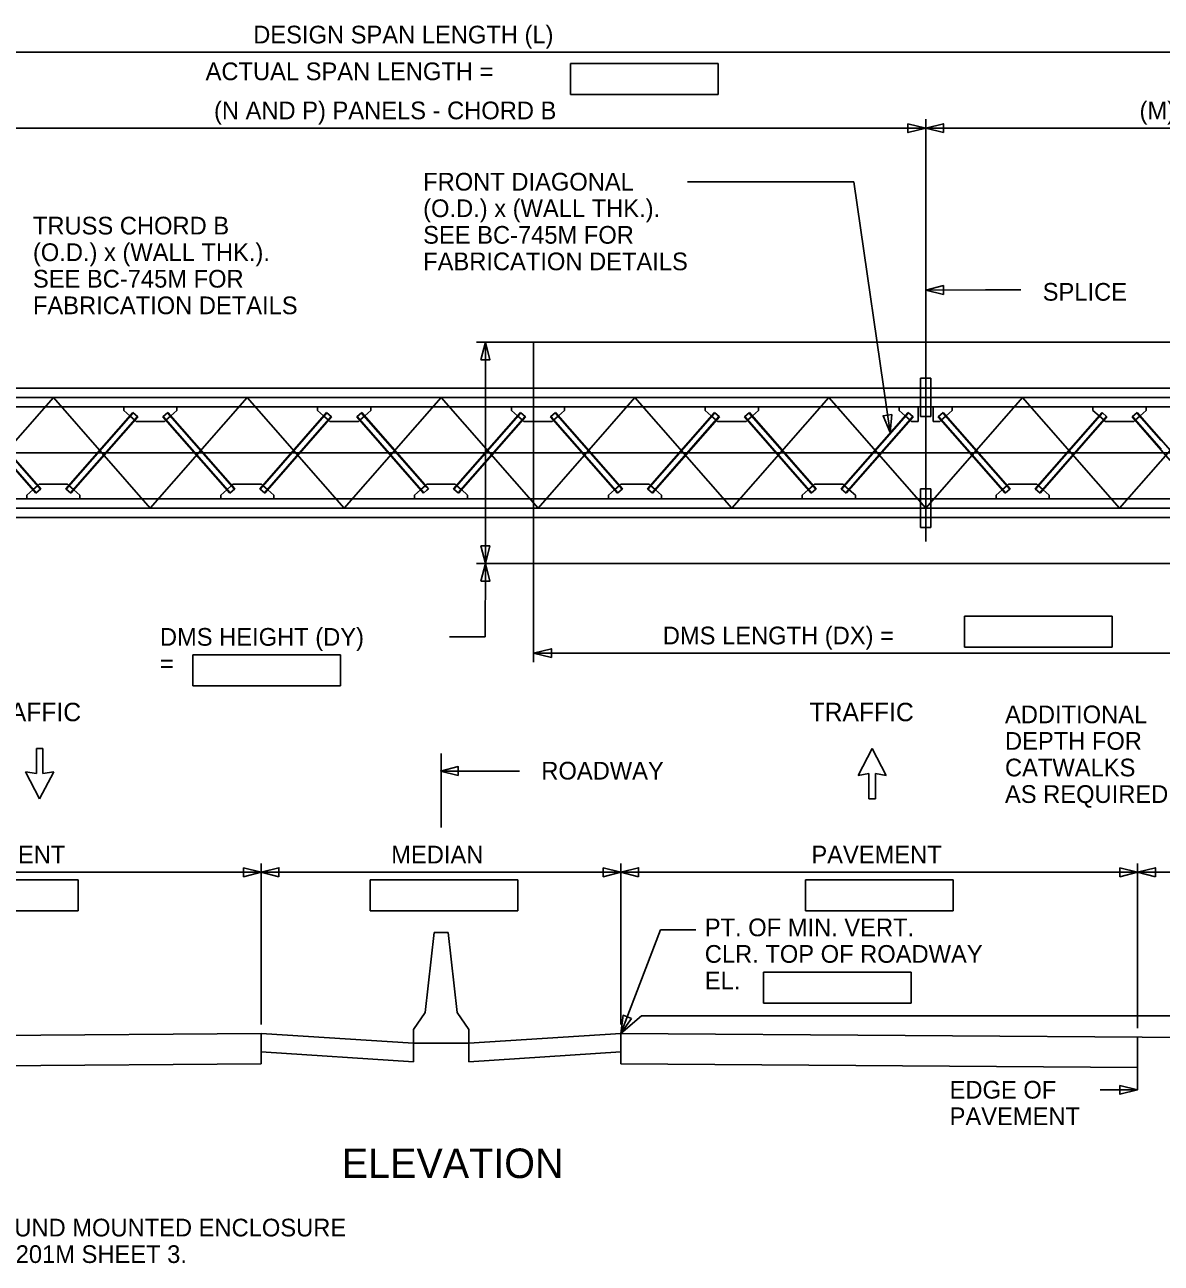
# Model space of a CAD drawing. Extents: x 3831399 to 3833095, y 499014 to 500202.
# Drawn here: x 3832471.3 to 3832657.9, y 499766.4 to 499969.9 of the extents above; entities that cross this region are included whole.
import ezdxf

# ---------------------------------------------------------------- set-up
doc = ezdxf.new("R2010")
doc.units = 0
for name, color, linetype in [('0-sign', 7, 'Continuous'), ('0-truss', 7, 'Continuous'), ('CenterLine', 7, 'Continuous'), ('Default', 7, 'Continuous'), ('DIM TXT', 7, 'Continuous'), ('grade', 7, 'Continuous')]:
    doc.layers.add(name, color=color, linetype=linetype)

msp = doc.modelspace()

# ---------------------------------------------------------------- linework, layer by layer
at = {"layer": '0-sign'}
for p, q in [((3832668.48, 499917.74), (3832554.81, 499917.74)), ((3832554.81, 499917.74), (3832554.81, 499881.36)), ((3832554.81, 499881.36), (3832668.48, 499881.36))]:
    msp.add_line(p, q, dxfattribs=at)
at = {"layer": '0-truss'}
for p, q in [((3832619.18, 499911.79), (3832618.33, 499911.79)), ((3832618.33, 499911.79), (3832618.33, 499905.49)), ((3832619.18, 499905.49), (3832619.18, 499911.79)), ((3832619.18, 499911.79), (3832620.03, 499911.79)), ((3832619.18, 499905.49), (3832619.18, 499911.79)), ((3832620.03, 499911.79), (3832620.03, 499905.49)), ((3832460.9, 499910.16), (3832537.29, 499910.16)), ((3832537.29, 499910.16), (3832650.95, 499910.16)), ((3832537.29, 499910.16), (3832685.48, 499910.16)), ((3832460.9, 499907.13), (3832537.29, 499907.13)), ((3832537.29, 499907.13), (3832650.95, 499907.13)), ((3832537.29, 499907.13), (3832685.48, 499907.13)), ((3832617.95, 499904.71), (3832617.95, 499907.13)), ((3832620.41, 499904.71), (3832620.41, 499907.13)), ((3832650.95, 499907.13), (3832646.65, 499907.13)), ((3832646.65, 499907.13), (3832646.65, 499906.48)), ((3832473.08, 499892.92), (3832462.1, 499905.47)), ((3832462.16, 499905.52), (3832473.14, 499892.97)), ((3832462.86, 499906.13), (3832473.84, 499893.58)), ((3832462.92, 499906.18), (3832473.9, 499893.63)), ((3832489, 499906.18), (3832478.02, 499893.63)), ((3832489.05, 499906.13), (3832478.07, 499893.58)), ((3832489.76, 499905.52), (3832478.78, 499892.97)), ((3832478.84, 499892.92), (3832489.82, 499905.47)), ((3832487.52, 499906.48), (3832488.5, 499905.62)), ((3832488.5, 499905.62), (3832489.32, 499904.9)), ((3832489.82, 499905.47), (3832489, 499906.18)), ((3832489.32, 499904.9), (3832489.53, 499904.71)), ((3832493.93, 499905.47), (3832494.75, 499906.18)), ((3832504.91, 499892.92), (3832493.93, 499905.47)), ((3832493.99, 499905.52), (3832504.97, 499892.97)), ((3832494.21, 499904.71), (3832494.42, 499904.9)), ((3832494.42, 499904.9), (3832495.24, 499905.62)), ((3832494.69, 499906.13), (3832505.67, 499893.58)), ((3832494.75, 499906.18), (3832505.73, 499893.63)), ((3832495.24, 499905.62), (3832496.23, 499906.48)), ((3832520.82, 499906.18), (3832509.84, 499893.63)), ((3832520.88, 499906.13), (3832509.9, 499893.58)), ((3832521.58, 499905.52), (3832510.6, 499892.97)), ((3832510.66, 499892.92), (3832521.64, 499905.47)), ((3832519.34, 499906.48), (3832520.33, 499905.62)), ((3832520.33, 499905.62), (3832521.15, 499904.9)), ((3832521.64, 499905.47), (3832520.82, 499906.18)), ((3832521.15, 499904.9), (3832521.36, 499904.71)), ((3832525.76, 499905.47), (3832526.58, 499906.18)), ((3832536.74, 499892.92), (3832525.76, 499905.47)), ((3832525.81, 499905.52), (3832536.79, 499892.97)), ((3832526.04, 499904.71), (3832526.25, 499904.9)), ((3832526.25, 499904.9), (3832527.07, 499905.62)), ((3832526.52, 499906.13), (3832537.29, 499893.83)), ((3832526.58, 499906.18), (3832537.29, 499893.94)), ((3832527.07, 499905.62), (3832528.06, 499906.48)), ((3832552.65, 499906.18), (3832541.67, 499893.63)), ((3832552.71, 499906.13), (3832541.73, 499893.58)), ((3832553.41, 499905.52), (3832542.43, 499892.97)), ((3832542.49, 499892.92), (3832553.47, 499905.47)), ((3832552.15, 499905.62), (3832551.17, 499906.48)), ((3832552.97, 499904.9), (3832552.15, 499905.62)), ((3832553.47, 499905.47), (3832552.65, 499906.18)), ((3832553.19, 499904.71), (3832552.97, 499904.9)), ((3832557.58, 499905.47), (3832558.4, 499906.18)), ((3832568.56, 499892.92), (3832557.58, 499905.47)), ((3832557.64, 499905.52), (3832568.62, 499892.97)), ((3832558.08, 499904.9), (3832557.87, 499904.71)), ((3832558.9, 499905.62), (3832558.08, 499904.9)), ((3832558.35, 499906.13), (3832569.33, 499893.58)), ((3832558.4, 499906.18), (3832569.38, 499893.63)), ((3832559.88, 499906.48), (3832558.9, 499905.62)), ((3832584.48, 499906.18), (3832573.5, 499893.63)), ((3832584.54, 499906.13), (3832573.56, 499893.58)), ((3832585.24, 499905.52), (3832574.26, 499892.97)), ((3832574.32, 499892.92), (3832585.3, 499905.47)), ((3832583.98, 499905.62), (3832583, 499906.48)), ((3832584.8, 499904.9), (3832583.98, 499905.62)), ((3832585.3, 499905.47), (3832584.48, 499906.18)), ((3832585.02, 499904.71), (3832584.8, 499904.9)), ((3832589.41, 499905.47), (3832590.23, 499906.18)), ((3832600.39, 499892.92), (3832589.41, 499905.47)), ((3832589.47, 499905.52), (3832600.45, 499892.97)), ((3832589.91, 499904.9), (3832589.69, 499904.71)), ((3832590.73, 499905.62), (3832589.91, 499904.9)), ((3832590.17, 499906.13), (3832601.15, 499893.58)), ((3832590.23, 499906.18), (3832601.21, 499893.63)), ((3832591.71, 499906.48), (3832590.73, 499905.62)), ((3832616.3, 499906.18), (3832605.32, 499893.63)), ((3832616.36, 499906.13), (3832605.38, 499893.58)), ((3832617.07, 499905.52), (3832606.09, 499892.97)), ((3832606.14, 499892.92), (3832617.12, 499905.47)), ((3832614.82, 499906.48), (3832615.81, 499905.62)), ((3832616.63, 499904.9), (3832615.81, 499905.62)), ((3832617.12, 499905.47), (3832616.3, 499906.18)), ((3832616.63, 499904.9), (3832616.84, 499904.71)), ((3832616.84, 499904.71), (3832617.95, 499904.71)), ((3832617.95, 499904.71), (3832617.95, 499904.71)), ((3832618.33, 499905.49), (3832619.18, 499905.49)), ((3832620.03, 499905.49), (3832619.18, 499905.49)), ((3832621.52, 499904.71), (3832620.41, 499904.71)), ((3832620.41, 499904.71), (3832620.41, 499904.71)), ((3832621.24, 499905.47), (3832622.06, 499906.18)), ((3832632.22, 499892.92), (3832621.24, 499905.47)), ((3832621.3, 499905.52), (3832632.28, 499892.97)), ((3832621.73, 499904.9), (3832621.52, 499904.71)), ((3832621.73, 499904.9), (3832622.55, 499905.62)), ((3832622, 499906.13), (3832632.98, 499893.58)), ((3832622.06, 499906.18), (3832633.04, 499893.63)), ((3832623.54, 499906.48), (3832622.55, 499905.62)), ((3832648.13, 499906.18), (3832637.15, 499893.63)), ((3832648.19, 499906.13), (3832637.21, 499893.58)), ((3832648.89, 499905.52), (3832637.91, 499892.97)), ((3832637.97, 499892.92), (3832648.95, 499905.47)), ((3832646.65, 499906.48), (3832647.64, 499905.62)), ((3832647.64, 499905.62), (3832648.46, 499904.9)), ((3832648.95, 499905.47), (3832648.13, 499906.18)), ((3832648.46, 499904.9), (3832648.67, 499904.71)), ((3832648.67, 499904.71), (3832650.95, 499904.71)), ((3832653.07, 499905.47), (3832653.89, 499906.18)), ((3832657.84, 499900.01), (3832653.07, 499905.47)), ((3832653.12, 499905.52), (3832657.84, 499900.13)), ((3832653.35, 499904.71), (3832653.56, 499904.9)), ((3832653.56, 499904.9), (3832654.38, 499905.62)), ((3832653.83, 499906.13), (3832657.84, 499901.55)), ((3832653.89, 499906.18), (3832657.84, 499901.66)), ((3832654.38, 499905.62), (3832655.37, 499906.48)), ((3832657.84, 499901.66), (3832659.33, 499899.96)), ((3832657.84, 499900.01), (3832659.33, 499898.3)), ((3832472.59, 499893.48), (3832471.6, 499892.62)), ((3832472.59, 499893.48), (3832473.41, 499894.2)), ((3832473.9, 499893.63), (3832473.08, 499892.92)), ((3832473.62, 499894.39), (3832473.41, 499894.2)), ((3832478.02, 499893.63), (3832478.84, 499892.92)), ((3832478.51, 499894.2), (3832478.3, 499894.39)), ((3832478.51, 499894.2), (3832479.33, 499893.48)), ((3832480.32, 499892.62), (3832479.33, 499893.48)), ((3832504.41, 499893.48), (3832503.43, 499892.62)), ((3832504.41, 499893.48), (3832505.23, 499894.2)), ((3832505.73, 499893.63), (3832504.91, 499892.92)), ((3832505.45, 499894.39), (3832505.23, 499894.2)), ((3832509.84, 499893.63), (3832510.66, 499892.92)), ((3832510.34, 499894.2), (3832510.12, 499894.39)), ((3832510.34, 499894.2), (3832511.16, 499893.48)), ((3832512.14, 499892.62), (3832511.16, 499893.48)), ((3832535.26, 499892.62), (3832536.24, 499893.48)), ((3832536.24, 499893.48), (3832537.06, 499894.2)), ((3832537.29, 499893.4), (3832536.74, 499892.92)), ((3832537.06, 499894.2), (3832537.27, 499894.39)), ((3832537.29, 499894.39), (3832541.95, 499894.39)), ((3832537.29, 499893.94), (3832537.56, 499893.63)), ((3832537.56, 499893.63), (3832537.29, 499893.4)), ((3832541.67, 499893.63), (3832542.49, 499892.92)), ((3832541.95, 499894.39), (3832542.17, 499894.2)), ((3832542.99, 499893.48), (3832542.17, 499894.2)), ((3832542.96, 499893.5), (3832543.97, 499892.62)), ((3832543.97, 499892.62), (3832543.97, 499891.97)), ((3832567.08, 499892.62), (3832568.07, 499893.48)), ((3832568.89, 499894.2), (3832568.07, 499893.48)), ((3832569.38, 499893.63), (3832568.56, 499892.92)), ((3832568.89, 499894.2), (3832569.1, 499894.39)), ((3832573.5, 499893.63), (3832574.32, 499892.92)), ((3832573.78, 499894.39), (3832573.99, 499894.2)), ((3832574.81, 499893.48), (3832573.99, 499894.2)), ((3832574.81, 499893.48), (3832575.8, 499892.62)), ((3832598.91, 499892.62), (3832599.9, 499893.48)), ((3832600.72, 499894.2), (3832599.9, 499893.48)), ((3832601.21, 499893.63), (3832600.39, 499892.92)), ((3832600.72, 499894.2), (3832600.93, 499894.39)), ((3832605.32, 499893.63), (3832606.14, 499892.92)), ((3832605.61, 499894.39), (3832605.82, 499894.2)), ((3832606.64, 499893.48), (3832605.82, 499894.2)), ((3832606.64, 499893.48), (3832607.63, 499892.62)), ((3832618.33, 499893.61), (3832619.18, 499893.61)), ((3832618.33, 499887.31), (3832618.33, 499893.61)), ((3832620.03, 499893.61), (3832619.18, 499893.61)), ((3832619.18, 499893.61), (3832619.18, 499887.31)), ((3832619.18, 499893.61), (3832619.18, 499887.31)), ((3832620.03, 499887.31), (3832620.03, 499893.61)), ((3832631.72, 499893.48), (3832630.74, 499892.62)), ((3832631.72, 499893.48), (3832632.54, 499894.2)), ((3832633.04, 499893.63), (3832632.22, 499892.92)), ((3832632.76, 499894.39), (3832632.54, 499894.2)), ((3832637.15, 499893.63), (3832637.97, 499892.92)), ((3832637.65, 499894.2), (3832637.43, 499894.39)), ((3832637.65, 499894.2), (3832638.47, 499893.48)), ((3832639.45, 499892.62), (3832638.47, 499893.48)), ((3832460.9, 499891.97), (3832537.29, 499891.97)), ((3832537.29, 499891.97), (3832650.95, 499891.97)), ((3832537.29, 499891.97), (3832685.48, 499891.97)), ((3832543.97, 499891.97), (3832537.29, 499891.97)), ((3832460.9, 499888.94), (3832537.29, 499888.94)), ((3832537.29, 499888.94), (3832650.95, 499888.94)), ((3832537.29, 499888.94), (3832650.95, 499888.94)), ((3832650.95, 499888.94), (3832685.48, 499888.94)), ((3832619.18, 499887.31), (3832618.33, 499887.31)), ((3832619.18, 499887.31), (3832620.03, 499887.31))]:
    msp.add_line(p, q, dxfattribs=at)
for points in [[(3832496.23, 499906.48), (3832496.23, 499907.13), (3832487.52, 499907.13), (3832487.52, 499906.48)], [(3832528.06, 499906.48), (3832528.06, 499907.13), (3832519.34, 499907.13), (3832519.34, 499906.48)], [(3832551.17, 499906.48), (3832551.17, 499907.13), (3832559.88, 499907.13), (3832559.88, 499906.48)], [(3832583, 499906.48), (3832583, 499907.13), (3832591.71, 499907.13), (3832591.71, 499906.48)], [(3832617.95, 499907.13), (3832614.82, 499907.13), (3832614.82, 499906.48)], [(3832620.41, 499907.13), (3832623.54, 499907.13), (3832623.54, 499906.48)], [(3832655.37, 499906.48), (3832655.37, 499907.13), (3832650.95, 499907.13)], [(3832489.53, 499904.71), (3832494.21, 499904.71)], [(3832521.36, 499904.71), (3832526.04, 499904.71)], [(3832557.87, 499904.71), (3832553.19, 499904.71)], [(3832589.69, 499904.71), (3832585.02, 499904.71)], [(3832650.95, 499904.71), (3832653.35, 499904.71)], [(3832471.6, 499892.62), (3832471.6, 499891.97), (3832480.32, 499891.97), (3832480.32, 499892.62)], [(3832478.3, 499894.39), (3832473.62, 499894.39)], [(3832503.43, 499892.62), (3832503.43, 499891.97), (3832512.14, 499891.97), (3832512.14, 499892.62)], [(3832510.12, 499894.39), (3832505.45, 499894.39)], [(3832537.29, 499891.97), (3832535.26, 499891.97), (3832535.26, 499892.62)], [(3832537.27, 499894.39), (3832537.29, 499894.39)], [(3832575.8, 499892.62), (3832575.8, 499891.97), (3832567.08, 499891.97), (3832567.08, 499892.62)], [(3832569.1, 499894.39), (3832573.78, 499894.39)], [(3832607.63, 499892.62), (3832607.63, 499891.97), (3832598.91, 499891.97), (3832598.91, 499892.62)], [(3832600.93, 499894.39), (3832605.61, 499894.39)], [(3832630.74, 499892.62), (3832630.74, 499891.97), (3832639.45, 499891.97), (3832639.45, 499892.62)], [(3832637.43, 499894.39), (3832632.76, 499894.39)]]:
    msp.add_lwpolyline(points, dxfattribs=at)
at = {"layer": 'CenterLine'}
for p, q in [((3832619.18, 499936.04), (3832619.18, 499885)), ((3832332.74, 499908.64), (3832746.49, 499908.64)), ((3832475.96, 499908.64), (3832460.05, 499890.46)), ((3832475.96, 499908.64), (3832491.87, 499890.46)), ((3832507.79, 499908.64), (3832491.87, 499890.46)), ((3832507.79, 499908.64), (3832523.7, 499890.46)), ((3832539.61, 499908.64), (3832523.7, 499890.46)), ((3832539.61, 499908.64), (3832555.53, 499890.46)), ((3832571.44, 499908.64), (3832555.53, 499890.46)), ((3832571.44, 499908.64), (3832587.35, 499890.46)), ((3832603.27, 499908.64), (3832587.35, 499890.46)), ((3832603.27, 499908.64), (3832619.18, 499890.46)), ((3832635.1, 499908.64), (3832619.18, 499890.46)), ((3832635.1, 499908.64), (3832651.01, 499890.46)), ((3832666.92, 499908.64), (3832651.01, 499890.46)), ((3832308.87, 499899.55), (3832771.9, 499899.55)), ((3832332.74, 499890.46), (3832746.49, 499890.46))]:
    msp.add_line(p, q, dxfattribs=at)
at = {"layer": 'Default'}
for p, q in [((3832560.85, 499963.52), (3832585.1, 499963.52)), ((3832560.85, 499958.43), (3832560.85, 499963.52)), ((3832585.1, 499963.52), (3832585.1, 499958.43)), ((3832585.1, 499958.43), (3832560.85, 499958.43)), ((3832625.55, 499872.74), (3832649.8, 499872.74)), ((3832625.55, 499867.65), (3832625.55, 499872.74)), ((3832649.8, 499872.74), (3832649.8, 499867.65)), ((3832498.87, 499866.36), (3832523.12, 499866.36)), ((3832498.87, 499861.26), (3832498.87, 499866.36)), ((3832523.12, 499866.36), (3832523.12, 499861.26)), ((3832649.8, 499867.65), (3832625.55, 499867.65)), ((3832523.12, 499861.26), (3832498.87, 499861.26)), ((3832539.61, 499838.03), (3832539.61, 499850.15)), ((3832455.78, 499829.38), (3832480.03, 499829.38)), ((3832480.03, 499829.38), (3832480.03, 499824.29)), ((3832527.96, 499829.38), (3832552.21, 499829.38)), ((3832527.96, 499824.29), (3832527.96, 499829.38)), ((3832552.21, 499829.38), (3832552.21, 499824.29)), ((3832599.43, 499829.38), (3832623.68, 499829.38)), ((3832599.43, 499824.29), (3832599.43, 499829.38)), ((3832623.68, 499829.38), (3832623.68, 499824.29)), ((3832480.03, 499824.29), (3832455.78, 499824.29)), ((3832552.21, 499824.29), (3832527.96, 499824.29)), ((3832623.68, 499824.29), (3832599.43, 499824.29)), ((3832592.55, 499814.26), (3832616.8, 499814.26)), ((3832592.55, 499809.16), (3832592.55, 499814.26)), ((3832616.8, 499814.26), (3832616.8, 499809.16)), ((3832616.8, 499809.16), (3832592.55, 499809.16))]:
    msp.add_line(p, q, dxfattribs=at)
at = {"layer": 'DIM TXT'}
for p, q in [((3832332.74, 499965.35), (3832746.37, 499965.35)), ((3832619.18, 499954.34), (3832619.18, 499954.34)), ((3832619.18, 499936.04), (3832619.18, 499954.34)), ((3832460.05, 499952.88), (3832619.18, 499952.88)), ((3832619.18, 499952.88), (3832746.49, 499952.88)), ((3832601.55, 499944.09), (3832580.07, 499944.09)), ((3832601.55, 499944.09), (3832607.37, 499944.09)), ((3832613.33, 499902.87), (3832607.37, 499944.09)), ((3832619.18, 499926.27), (3832628.98, 499926.32)), ((3832634.8, 499926.32), (3832628.98, 499926.32)), ((3832554.81, 499917.74), (3832545.43, 499917.74)), ((3832546.89, 499917.74), (3832546.89, 499881.36)), ((3832554.81, 499881.36), (3832545.43, 499881.36)), ((3832546.89, 499881.36), (3832546.83, 499869.32)), ((3832554.81, 499881.36), (3832554.81, 499865.18)), ((3832541.01, 499869.32), (3832546.83, 499869.32)), ((3832554.81, 499866.64), (3832668.48, 499866.64)), ((3832474.22, 499850.98), (3832473.17, 499850.98)), ((3832473.17, 499850.98), (3832473.17, 499846.85)), ((3832474.22, 499846.85), (3832474.22, 499850.98)), ((3832608.08, 499846.56), (3832610.4, 499850.98)), ((3832610.4, 499850.98), (3832612.71, 499846.56)), ((3832473.17, 499846.85), (3832471.38, 499847.15)), ((3832471.38, 499847.15), (3832473.69, 499842.73)), ((3832473.69, 499842.73), (3832476.01, 499847.15)), ((3832476.01, 499847.15), (3832474.22, 499846.85)), ((3832539.53, 499847.27), (3832546.65, 499847.27)), ((3832552.47, 499847.27), (3832546.65, 499847.27)), ((3832609.87, 499846.85), (3832608.08, 499846.56)), ((3832609.87, 499842.73), (3832609.87, 499846.85)), ((3832610.92, 499846.85), (3832610.92, 499842.73)), ((3832612.71, 499846.56), (3832610.92, 499846.85)), ((3832610.92, 499842.73), (3832609.87, 499842.73)), ((3832510.09, 499805.63), (3832510.09, 499832.1)), ((3832510.09, 499807.08), (3832510.09, 499832.1)), ((3832569.14, 499805.63), (3832569.14, 499832.1)), ((3832569.14, 499807.08), (3832569.14, 499832.1)), ((3832653.98, 499805.02), (3832653.98, 499832.1)), ((3832653.98, 499806.48), (3832653.98, 499832.1)), ((3832510.09, 499830.65), (3832425.25, 499830.65)), ((3832510.09, 499830.65), (3832569.14, 499830.65)), ((3832569.14, 499830.65), (3832653.98, 499830.65)), ((3832653.98, 499830.65), (3832697.19, 499830.65)), ((3832569.14, 499804.17), (3832575.64, 499821.22)), ((3832581.46, 499821.22), (3832575.64, 499821.22)), ((3832569.14, 499804.17), (3832572.52, 499807.09)), ((3832572.52, 499807.09), (3832680.32, 499807.09)), ((3832653.98, 499798.56), (3832653.98, 499794.93)), ((3832647.84, 499794.93), (3832653.66, 499794.93)), ((3832653.98, 499794.93), (3832653.66, 499794.93))]:
    msp.add_line(p, q, dxfattribs=at)
for points in [[(3832616.27, 499953.61), (3832619.18, 499952.88), (3832616.27, 499952.16)], [(3832622.09, 499952.16), (3832619.18, 499952.88), (3832622.09, 499953.61)], [(3832622.1, 499925.55), (3832619.18, 499926.27), (3832622.09, 499927.01)], [(3832546.16, 499914.83), (3832546.89, 499917.74), (3832547.62, 499914.83)], [(3832613.63, 499905.85), (3832613.33, 499902.87), (3832612.19, 499905.64)], [(3832547.62, 499884.27), (3832546.89, 499881.36), (3832546.16, 499884.27)], [(3832546.15, 499878.46), (3832546.89, 499881.36), (3832547.6, 499878.45)], [(3832557.72, 499865.91), (3832554.81, 499866.64), (3832557.72, 499867.36)], [(3832542.44, 499846.54), (3832539.53, 499847.27), (3832542.44, 499848)], [(3832507.18, 499831.38), (3832510.09, 499830.65), (3832507.18, 499829.92)], [(3832513, 499829.92), (3832510.09, 499830.65), (3832513, 499831.38)], [(3832566.23, 499831.38), (3832569.14, 499830.65), (3832566.23, 499829.92)], [(3832572.05, 499829.92), (3832569.14, 499830.65), (3832572.05, 499831.38)], [(3832651.07, 499831.38), (3832653.98, 499830.65), (3832651.07, 499829.92)], [(3832656.89, 499829.92), (3832653.98, 499830.65), (3832656.89, 499831.38)], [(3832570.86, 499806.63), (3832569.14, 499804.17), (3832569.5, 499807.15)], [(3832651.06, 499795.65), (3832653.98, 499794.93), (3832651.07, 499794.19)]]:
    msp.add_lwpolyline(points, close=True, dxfattribs=at)
at = {"layer": 'grade'}
for p, q in [((3832536.98, 499807.61), (3832538.48, 499820.74)), ((3832540.75, 499820.74), (3832538.48, 499820.74)), ((3832539.61, 499820.74), (3832540.75, 499820.74)), ((3832542.25, 499807.61), (3832540.75, 499820.74)), ((3832535.07, 499804.83), (3832536.98, 499807.61)), ((3832544.16, 499804.83), (3832542.25, 499807.61)), ((3832352.64, 499803.05), (3832510.09, 499804.17)), ((3832510.09, 499804.17), (3832535.07, 499802.56)), ((3832510.09, 499799.16), (3832510.09, 499804.17)), ((3832535.07, 499802.56), (3832535.07, 499804.83)), ((3832544.16, 499802.56), (3832544.16, 499804.83)), ((3832569.14, 499804.17), (3832544.16, 499802.56)), ((3832726.58, 499803.05), (3832569.14, 499804.17)), ((3832569.14, 499801.14), (3832569.14, 499804.17)), ((3832569.14, 499799.16), (3832569.14, 499804.17)), ((3832653.98, 499798.67), (3832653.98, 499803.57)), ((3832653.98, 499798.56), (3832653.98, 499803.57)), ((3832510.09, 499801.14), (3832535.07, 499799.52)), ((3832539.61, 499802.56), (3832535.07, 499802.56)), ((3832535.07, 499802.56), (3832535.07, 499799.52)), ((3832539.61, 499802.56), (3832544.16, 499802.56)), ((3832544.16, 499802.56), (3832544.16, 499799.52)), ((3832569.14, 499801.14), (3832544.16, 499799.52)), ((3832425.25, 499798.56), (3832510.09, 499799.16)), ((3832653.97, 499798.56), (3832569.14, 499799.16))]:
    msp.add_line(p, q, dxfattribs=at)

# ---------------------------------------------------------------- texts
at = {"layer": 'DIM TXT'}
for s, height, p in [('DESIGN SPAN LENGTH (L)', 2.9099, (3832508.77, 499966.8)), ('ACTUAL SPAN LENGTH = ', 2.9099, (3832500.95, 499960.76)), ('(N AND P) PANELS - CHORD B', 2.9099, (3832502.33, 499954.34)), ('(M) PANELS - CHORD C', 2.9099, (3832654.29, 499954.34)), ('FRONT DIAGONAL', 2.9099, (3832536.67, 499942.63)), ('(O.D.) x (WALL THK.).', 2.9099, (3832536.67, 499938.27)), ('TRUSS CHORD B', 2.9099, (3832472.6, 499935.42)), ('SEE BC-745M FOR', 2.9099, (3832536.67, 499933.9)), ('(O.D.) x (WALL THK.).', 2.9099, (3832472.6, 499931.05)), ('FABRICATION DETAILS', 2.9099, (3832536.67, 499929.54)), ('SEE BC-745M FOR', 2.9099, (3832472.6, 499926.69)), ('  SPLICE', 2.91, (3832636.23, 499924.54)), ('FABRICATION DETAILS', 2.9099, (3832472.6, 499922.32)), ('DMS HEIGHT (DY)', 2.9099, (3832493.45, 499867.86)), ('DMS LENGTH (DX) =        ', 2.9099, (3832576.02, 499868.09)), ('=', 2.91, (3832493.45, 499863.5)), ('TRAFFIC', 3.031, (3832463.4, 499855.46)), ('TRAFFIC', 3.031, (3832600.11, 499855.46)), ('ADDITIONAL', 2.91, (3832632.2, 499855.13)), ('DEPTH FOR', 2.91, (3832632.2, 499850.77)), ('  ROADWAY', 2.91, (3832553.91, 499845.88)), ('CATWALKS ', 2.91, (3832632.2, 499846.4)), ('AS REQUIRED', 2.9099, (3832632.2, 499842.04)), ('PAVEMENT', 2.91, (3832456.52, 499832.1)), ('MEDIAN', 2.91, (3832531.43, 499832.1)), ('PAVEMENT', 2.91, (3832600.41, 499832.1)), ('PT. OF MIN. VERT. ', 2.9099, (3832582.91, 499820.14)), ('CLR. TOP OF ROADWAY', 2.9099, (3832582.91, 499815.78)), ('EL. ', 2.91, (3832582.91, 499811.41)), ('EDGE OF', 2.91, (3832623.11, 499793.47)), ('PAVEMENT', 2.91, (3832623.11, 499789.11)), ('ELEVATION', 4.85, (3832523.31, 499780.42)), ('FOR GROUND MOUNTED ENCLOSURE', 2.9099, (3832451.39, 499770.83)), ('SEE ITS-1201M SHEET 3.', 2.9099, (3832451.39, 499766.47))]:
    msp.add_text(s, height=height, dxfattribs=at).set_placement(p)

doc.saveas('drawing.dxf')
